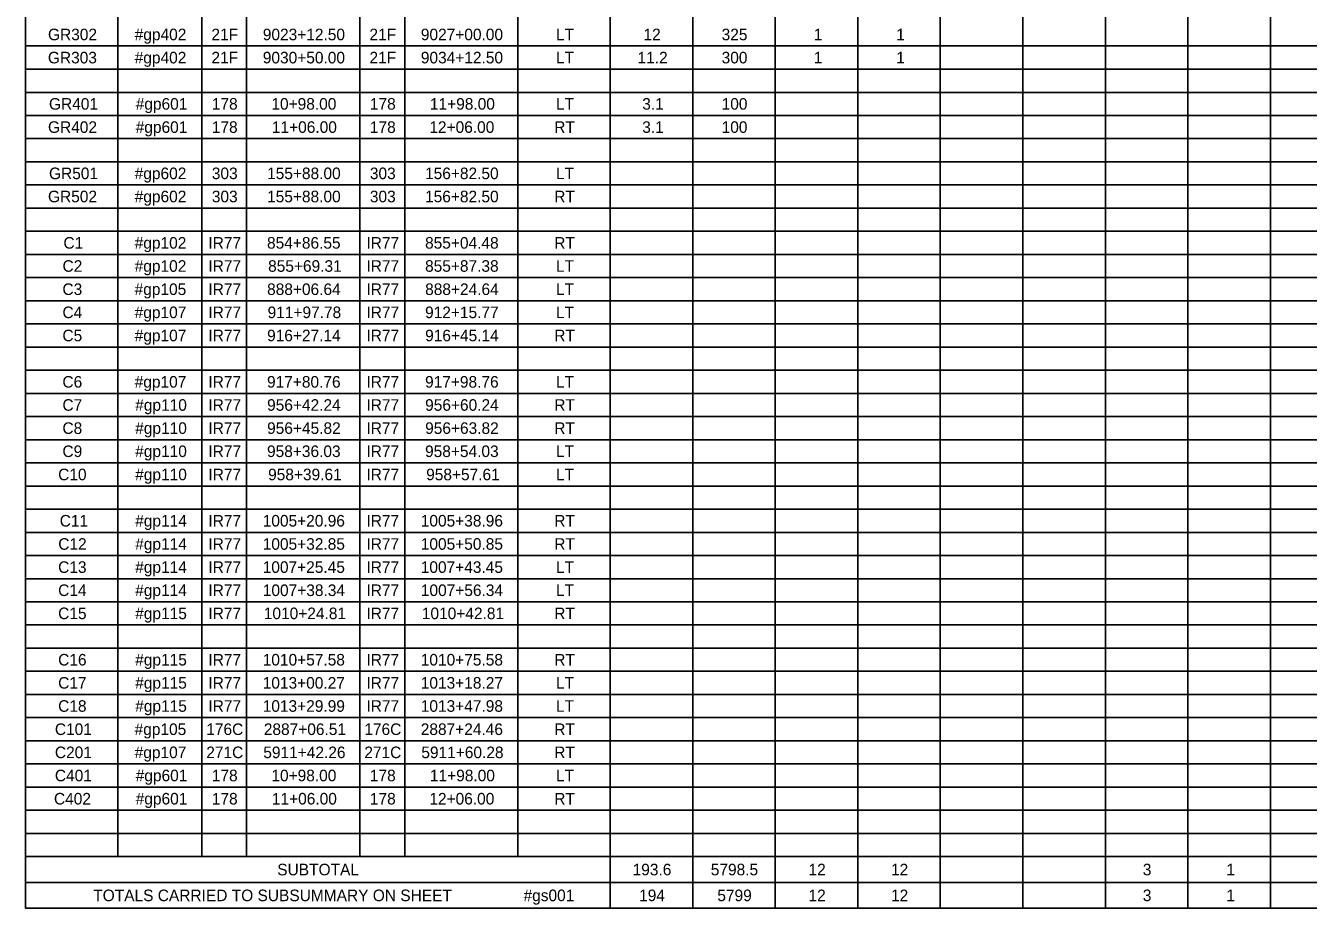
# Model space of a CAD drawing. Extents: x -542 to 295, y -281 to 32.
# Drawn here: x -16.36 to -1.11, y -130.59 to -120.1 of the extents above; entities that cross this region are included whole.
import ezdxf

# ---------------------------------------------------------------- set-up
doc = ezdxf.new("R2010")
doc.units = 0
doc.layers.add('SC_Scratch1', color=7, linetype='Continuous')
doc.layers.add('SH_Text', color=7, linetype='Continuous')

msp = doc.modelspace()

# ---------------------------------------------------------------- linework, layer by layer
at = {"layer": 'SC_Scratch1'}
msp.add_lwpolyline([(-16.359, -109.593), (14.141, -109.593), (14.141, -130.593), (-16.359, -130.593)], close=True, dxfattribs=at)
at = {"layer": 'SH_Text'}
for p, q in [((-16.359, -109.593), (-16.359, -130.594)), ((-15.261, -109.593), (-15.261, -129.979)), ((-14.263, -109.593), (-14.263, -129.979)), ((-10.506, -109.593), (-10.506, -129.979)), ((-9.408, -109.593), (-9.408, -130.594)), ((-8.427, -109.593), (-8.427, -130.594)), ((-7.446, -109.593), (-7.446, -130.594)), ((-6.465, -109.593), (-6.465, -130.594)), ((-5.484, -109.593), (-5.484, -130.594)), ((-4.503, -109.593), (-4.503, -130.594)), ((-3.522, -109.593), (-3.522, -130.594)), ((-2.541, -109.593), (-2.541, -130.594)), ((-1.56, -109.593), (-1.56, -130.594)), ((-12.385, -112.847), (-12.385, -129.979)), ((-13.731, -113.187), (-13.731, -129.979)), ((-11.852, -113.187), (-11.852, -129.979)), ((-16.359, -120.344), (14.136, -120.344)), ((-16.359, -120.62), (14.136, -120.62)), ((-16.359, -120.895), (14.136, -120.895)), ((-16.359, -121.17), (14.136, -121.17)), ((-16.359, -121.445), (14.136, -121.445)), ((-16.359, -121.721), (14.136, -121.721)), ((-16.359, -121.996), (14.136, -121.996)), ((-16.359, -122.271), (14.136, -122.271)), ((-16.359, -122.547), (14.136, -122.547)), ((-16.359, -122.822), (14.136, -122.822)), ((-16.359, -123.097), (14.136, -123.097)), ((-16.359, -123.372), (14.136, -123.372)), ((-16.359, -123.648), (14.136, -123.648)), ((-16.359, -123.923), (14.136, -123.923)), ((-16.359, -124.198), (14.136, -124.198)), ((-16.359, -124.473), (14.136, -124.473)), ((-16.359, -124.749), (14.136, -124.749)), ((-16.359, -125.024), (14.136, -125.024)), ((-16.359, -125.299), (14.136, -125.299)), ((-16.359, -125.575), (14.136, -125.575)), ((-16.359, -125.85), (14.136, -125.85)), ((-16.359, -126.125), (14.136, -126.125)), ((-16.359, -126.4), (14.136, -126.4)), ((-16.359, -126.676), (14.136, -126.676)), ((-16.359, -126.951), (14.136, -126.951)), ((-16.359, -127.226), (14.136, -127.226)), ((-16.359, -127.501), (14.136, -127.501)), ((-16.359, -127.777), (14.136, -127.777)), ((-16.359, -128.052), (14.136, -128.052)), ((-16.359, -128.327), (14.136, -128.327)), ((-16.359, -128.603), (14.136, -128.603)), ((-16.359, -128.878), (14.136, -128.878)), ((-16.359, -129.153), (14.136, -129.153)), ((-16.359, -129.428), (14.136, -129.428)), ((-16.359, -129.704), (14.136, -129.704)), ((-16.359, -129.979), (14.136, -129.979)), ((-16.359, -130.287), (14.136, -130.287)), ((-16.359, -130.594), (14.136, -130.594))]:
    msp.add_line(p, q, dxfattribs=at)

# ---------------------------------------------------------------- texts
for s, height, p in [('GR302', 0.1376, (-16.093, -120.276)), ('#gp402', 0.1376, (-15.062, -120.276)), ('21F', 0.1376, (-14.15, -120.276)), ('9023+12.50', 0.1376, (-13.539, -120.276)), ('21F', 0.1376, (-12.271, -120.276)), ('9027+00.00', 0.1376, (-11.66, -120.276)), ('LT', 0.1376, (-10.054, -120.276)), ('12', 0.1376, (-9.013, -120.276)), ('325', 0.1376, (-8.084, -120.276)), ('1', 0.138, (-6.989, -120.276)), ('1', 0.138, (-6.008, -120.276)), ('GR303', 0.1376, (-16.094, -120.551)), ('#gp402', 0.1376, (-15.062, -120.551)), ('21F', 0.1376, (-14.15, -120.551)), ('9030+50.00', 0.1376, (-13.539, -120.551)), ('21F', 0.1376, (-12.271, -120.551)), ('9034+12.50', 0.1376, (-11.66, -120.551)), ('LT', 0.1376, (-10.054, -120.551)), ('11.2', 0.1376, (-9.084, -120.551)), ('300', 0.1376, (-8.084, -120.551)), ('1', 0.138, (-6.989, -120.551)), ('1', 0.138, (-6.008, -120.551)), ('GR401', 0.1376, (-16.081, -121.101)), ('#gp601', 0.1376, (-15.05, -121.101)), ('178', 0.1376, (-14.145, -121.101)), ('10+98.00', 0.1376, (-13.437, -121.101)), ('178', 0.1376, (-12.266, -121.101)), ('11+98.00', 0.1376, (-11.552, -121.101)), ('LT', 0.1376, (-10.054, -121.101)), ('3.1', 0.1376, (-9.028, -121.101)), ('100', 0.1376, (-8.084, -121.101)), ('GR402', 0.1376, (-16.093, -121.377)), ('#gp601', 0.1376, (-15.05, -121.377)), ('178', 0.1376, (-14.145, -121.377)), ('11+06.00', 0.1376, (-13.431, -121.377)), ('178', 0.1376, (-12.266, -121.377)), ('12+06.00', 0.1376, (-11.559, -121.377)), ('3.1', 0.1376, (-9.028, -121.377)), ('100', 0.1376, (-8.084, -121.377)), ('RT', 0.1376, (-10.074, -121.377)), ('GR501', 0.1376, (-16.081, -121.927)), ('#gp602', 0.1376, (-15.062, -121.927)), ('303', 0.1376, (-14.145, -121.927)), ('155+88.00', 0.1376, (-13.488, -121.927)), ('303', 0.1376, (-12.266, -121.927)), ('156+82.50', 0.1376, (-11.61, -121.927)), ('LT', 0.1376, (-10.054, -121.927)), ('GR502', 0.1376, (-16.093, -122.202)), ('#gp602', 0.1376, (-15.062, -122.202)), ('303', 0.1376, (-14.145, -122.202)), ('155+88.00', 0.1376, (-13.488, -122.202)), ('303', 0.1376, (-12.266, -122.202)), ('156+82.50', 0.1376, (-11.61, -122.202)), ('RT', 0.1376, (-10.074, -122.202)), ('C1', 0.1376, (-15.909, -122.753)), ('#gp102', 0.1376, (-15.062, -122.753)), ('IR77', 0.1376, (-14.186, -122.753)), ('854+86.55', 0.1376, (-13.489, -122.753)), ('IR77', 0.1376, (-12.307, -122.753)), ('855+04.48', 0.1376, (-11.61, -122.753)), ('RT', 0.1376, (-10.074, -122.753)), ('C2', 0.1376, (-15.92, -123.028)), ('#gp102', 0.1376, (-15.062, -123.028)), ('IR77', 0.1376, (-14.186, -123.028)), ('855+69.31', 0.1376, (-13.476, -123.028)), ('IR77', 0.1376, (-12.307, -123.028)), ('855+87.38', 0.1376, (-11.61, -123.028)), ('LT', 0.1376, (-10.054, -123.028)), ('C3', 0.1376, (-15.921, -123.304)), ('#gp105', 0.1376, (-15.063, -123.304)), ('IR77', 0.1376, (-14.186, -123.304)), ('888+06.64', 0.1376, (-13.488, -123.304)), ('IR77', 0.1376, (-12.307, -123.304)), ('888+24.64', 0.1376, (-11.609, -123.304)), ('LT', 0.1376, (-10.054, -123.304)), ('C4', 0.1376, (-15.921, -123.579)), ('#gp107', 0.1376, (-15.062, -123.579)), ('IR77', 0.1376, (-14.186, -123.579)), ('911+97.78', 0.1376, (-13.482, -123.579)), ('IR77', 0.1376, (-12.307, -123.579)), ('912+15.77', 0.1376, (-11.61, -123.579)), ('LT', 0.1376, (-10.054, -123.579)), ('C5', 0.1376, (-15.921, -123.854)), ('#gp107', 0.1376, (-15.062, -123.854)), ('IR77', 0.1376, (-14.186, -123.854)), ('916+27.14', 0.1376, (-13.488, -123.854)), ('IR77', 0.1376, (-12.307, -123.854)), ('916+45.14', 0.1376, (-11.609, -123.854)), ('RT', 0.1376, (-10.074, -123.854)), ('C6', 0.1376, (-15.921, -124.405)), ('#gp107', 0.1376, (-15.062, -124.405)), ('IR77', 0.1376, (-14.186, -124.405)), ('917+80.76', 0.1376, (-13.489, -124.405)), ('IR77', 0.1376, (-12.307, -124.405)), ('917+98.76', 0.1376, (-11.61, -124.405)), ('LT', 0.1376, (-10.054, -124.405)), ('C7', 0.1376, (-15.921, -124.68)), ('#gp110', 0.1376, (-15.056, -124.68)), ('IR77', 0.1376, (-14.186, -124.68)), ('956+42.24', 0.1376, (-13.488, -124.68)), ('IR77', 0.1376, (-12.307, -124.68)), ('956+60.24', 0.1376, (-11.609, -124.68)), ('RT', 0.1376, (-10.074, -124.68)), ('C8', 0.1376, (-15.921, -124.955)), ('#gp110', 0.1376, (-15.056, -124.955)), ('IR77', 0.1376, (-14.186, -124.955)), ('956+45.82', 0.1376, (-13.488, -124.955)), ('IR77', 0.1376, (-12.307, -124.955)), ('956+63.82', 0.1376, (-11.609, -124.955)), ('RT', 0.1376, (-10.074, -124.955)), ('C9', 0.1376, (-15.921, -125.23)), ('#gp110', 0.1376, (-15.056, -125.23)), ('IR77', 0.1376, (-14.186, -125.23)), ('958+36.03', 0.1376, (-13.489, -125.23)), ('IR77', 0.1376, (-12.307, -125.23)), ('958+54.03', 0.1376, (-11.61, -125.23)), ('LT', 0.1376, (-10.054, -125.23)), ('C10', 0.1376, (-15.972, -125.506)), ('#gp110', 0.1376, (-15.056, -125.506)), ('IR77', 0.1376, (-14.186, -125.506)), ('958+39.61', 0.1376, (-13.476, -125.506)), ('IR77', 0.1376, (-12.307, -125.506)), ('958+57.61', 0.1376, (-11.597, -125.506)), ('LT', 0.1376, (-10.054, -125.506)), ('C11', 0.1376, (-15.953, -126.056)), ('#gp114', 0.1376, (-15.056, -126.056)), ('IR77', 0.1376, (-14.186, -126.056)), ('1005+20.96', 0.1376, (-13.54, -126.056)), ('IR77', 0.1376, (-12.307, -126.056)), ('1005+38.96', 0.1376, (-11.661, -126.056)), ('RT', 0.1376, (-10.074, -126.056)), ('C12', 0.1376, (-15.971, -126.332)), ('#gp114', 0.1376, (-15.056, -126.332)), ('IR77', 0.1376, (-14.186, -126.332)), ('1005+32.85', 0.1376, (-13.54, -126.332)), ('IR77', 0.1376, (-12.307, -126.332)), ('1005+50.85', 0.1376, (-11.661, -126.332)), ('RT', 0.1376, (-10.074, -126.332)), ('C13', 0.1376, (-15.972, -126.607)), ('#gp114', 0.1376, (-15.056, -126.607)), ('IR77', 0.1376, (-14.186, -126.607)), ('1007+25.45', 0.1376, (-13.54, -126.607)), ('IR77', 0.1376, (-12.307, -126.607)), ('1007+43.45', 0.1376, (-11.661, -126.607)), ('LT', 0.1376, (-10.054, -126.607)), ('C14', 0.1376, (-15.972, -126.882)), ('#gp114', 0.1376, (-15.056, -126.882)), ('IR77', 0.1376, (-14.186, -126.882)), ('1007+38.34', 0.1376, (-13.539, -126.882)), ('IR77', 0.1376, (-12.307, -126.882)), ('1007+56.34', 0.1376, (-11.66, -126.882)), ('LT', 0.1376, (-10.054, -126.882)), ('C15', 0.1376, (-15.972, -127.157)), ('#gp115', 0.1376, (-15.056, -127.157)), ('IR77', 0.1376, (-14.186, -127.157)), ('1010+24.81', 0.1376, (-13.527, -127.157)), ('IR77', 0.1376, (-12.307, -127.157)), ('1010+42.81', 0.1376, (-11.648, -127.157)), ('RT', 0.1376, (-10.074, -127.157)), ('C16', 0.1376, (-15.972, -127.708)), ('#gp115', 0.1376, (-15.056, -127.708)), ('IR77', 0.1376, (-14.186, -127.708)), ('1010+57.58', 0.1376, (-13.54, -127.708)), ('IR77', 0.1376, (-12.307, -127.708)), ('1010+75.58', 0.1376, (-11.661, -127.708)), ('RT', 0.1376, (-10.074, -127.708)), ('C17', 0.1376, (-15.972, -127.983)), ('#gp115', 0.1376, (-15.056, -127.983)), ('IR77', 0.1376, (-14.186, -127.983)), ('1013+00.27', 0.1376, (-13.54, -127.983)), ('IR77', 0.1376, (-12.307, -127.983)), ('1013+18.27', 0.1376, (-11.661, -127.983)), ('LT', 0.1376, (-10.054, -127.983)), ('C18', 0.1376, (-15.972, -128.258)), ('#gp115', 0.1376, (-15.056, -128.258)), ('IR77', 0.1376, (-14.186, -128.258)), ('1013+29.99', 0.1376, (-13.54, -128.258)), ('IR77', 0.1376, (-12.307, -128.258)), ('1013+47.98', 0.1376, (-11.661, -128.258)), ('LT', 0.1376, (-10.054, -128.258)), ('C101', 0.1376, (-16.011, -128.534)), ('#gp105', 0.1376, (-15.063, -128.534)), ('176C', 0.1376, (-14.211, -128.534)), ('2887+06.51', 0.1376, (-13.527, -128.534)), ('176C', 0.1376, (-12.332, -128.534)), ('2887+24.46', 0.1376, (-11.661, -128.534)), ('RT', 0.1376, (-10.074, -128.534)), ('C201', 0.1376, (-16.011, -128.809)), ('#gp107', 0.1376, (-15.062, -128.809)), ('271C', 0.1376, (-14.211, -128.809)), ('5911+42.26', 0.1376, (-13.533, -128.809)), ('271C', 0.1376, (-12.332, -128.809)), ('5911+60.28', 0.1376, (-11.654, -128.809)), ('RT', 0.1376, (-10.074, -128.809)), ('C401', 0.1376, (-16.011, -129.084)), ('#gp601', 0.1376, (-15.05, -129.084)), ('178', 0.1376, (-14.145, -129.084)), ('10+98.00', 0.1376, (-13.437, -129.084)), ('178', 0.1376, (-12.266, -129.084)), ('11+98.00', 0.1376, (-11.552, -129.084)), ('LT', 0.1376, (-10.054, -129.084)), ('C402', 0.1376, (-16.022, -129.36)), ('#gp601', 0.1376, (-15.05, -129.36)), ('178', 0.1376, (-14.145, -129.36)), ('11+06.00', 0.1376, (-13.431, -129.36)), ('178', 0.1376, (-12.266, -129.36)), ('12+06.00', 0.1376, (-11.559, -129.36)), ('RT', 0.1376, (-10.074, -129.36)), ('SUBTOTAL', 0.1376, (-13.367, -130.202)), ('193.6', 0.1376, (-9.142, -130.202)), ('5798.5', 0.1376, (-8.213, -130.202)), ('12', 0.1376, (-7.051, -130.202)), ('12', 0.1376, (-6.07, -130.202)), ('3', 0.138, (-3.077, -130.202)), ('1', 0.138, (-2.084, -130.202)), ('TOTALS CARRIED TO SUBSUMMARY ON SHEET', 0.13764, (-15.555, -130.509)), ('#gs001', 0.1376, (-10.439, -130.509)), ('194', 0.1376, (-9.065, -130.509)), ('5799', 0.1376, (-8.135, -130.509)), ('12', 0.1376, (-7.051, -130.509)), ('12', 0.1376, (-6.07, -130.509)), ('3', 0.138, (-3.077, -130.509)), ('1', 0.138, (-2.084, -130.509))]:
    msp.add_text(s, height=height, dxfattribs=at).set_placement(p)

doc.saveas('drawing.dxf')
